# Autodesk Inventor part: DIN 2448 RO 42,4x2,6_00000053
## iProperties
Created: 2006-03
Part Number: DIN 2448 RO 42,4x2,6_00000053
Material: Default
Document SubType Name: Modeling
Designer: Carlo
Stock Number: DIN 2448 RO 42,4x2,6
Mass: 577.032 g
Surface Area: 4452.08 cm^2
Volume: 577.032 cm^3
Density: 1 g/cm^3
G_L: 1805.000 mm
G_W: 42.400 mm
G_H: 42.400 mm
AFG_Item: 42.4 x 2.6
CSToolsMass: 1.0
CSToolsVolume: 577032.0
CSToolsArea: 4452.0
Author: Carlo
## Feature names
1. AFG_Detailed_DIN 2448 RO 42,4x2,6_00000053 [Extrusion]
2. AFG_Simplified_DIN 2448 RO 42,4x2,6_00000053 [Extrusion]
3. AFG_StartExtrusion_1 [Extrusion]
4. AFG_StartExtrusion_2 [Extrusion]
5. AFG_EndExtrusion_1 [Extrusion]
6. AFG_EndExtrusion_2 [Extrusion]
